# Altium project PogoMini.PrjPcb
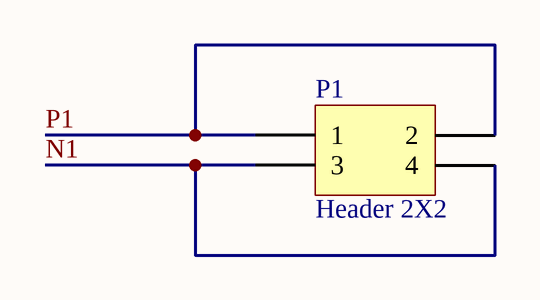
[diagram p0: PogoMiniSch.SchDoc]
1 sheet, 1 parts. Net scope: global (net labels, ports and power ports of the same name join across sheets).
Board file: 6C-2L-1550um.PcbDoc

## Sheet PogoMiniSch.SchDoc
size A4

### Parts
P1  Header 2X2  [HDR2X2]

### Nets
N1: P1.3 P1.4
P1: P1.1 P1.2

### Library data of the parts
P1 = Header 2X2: Header, 2-Pin, Dual row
